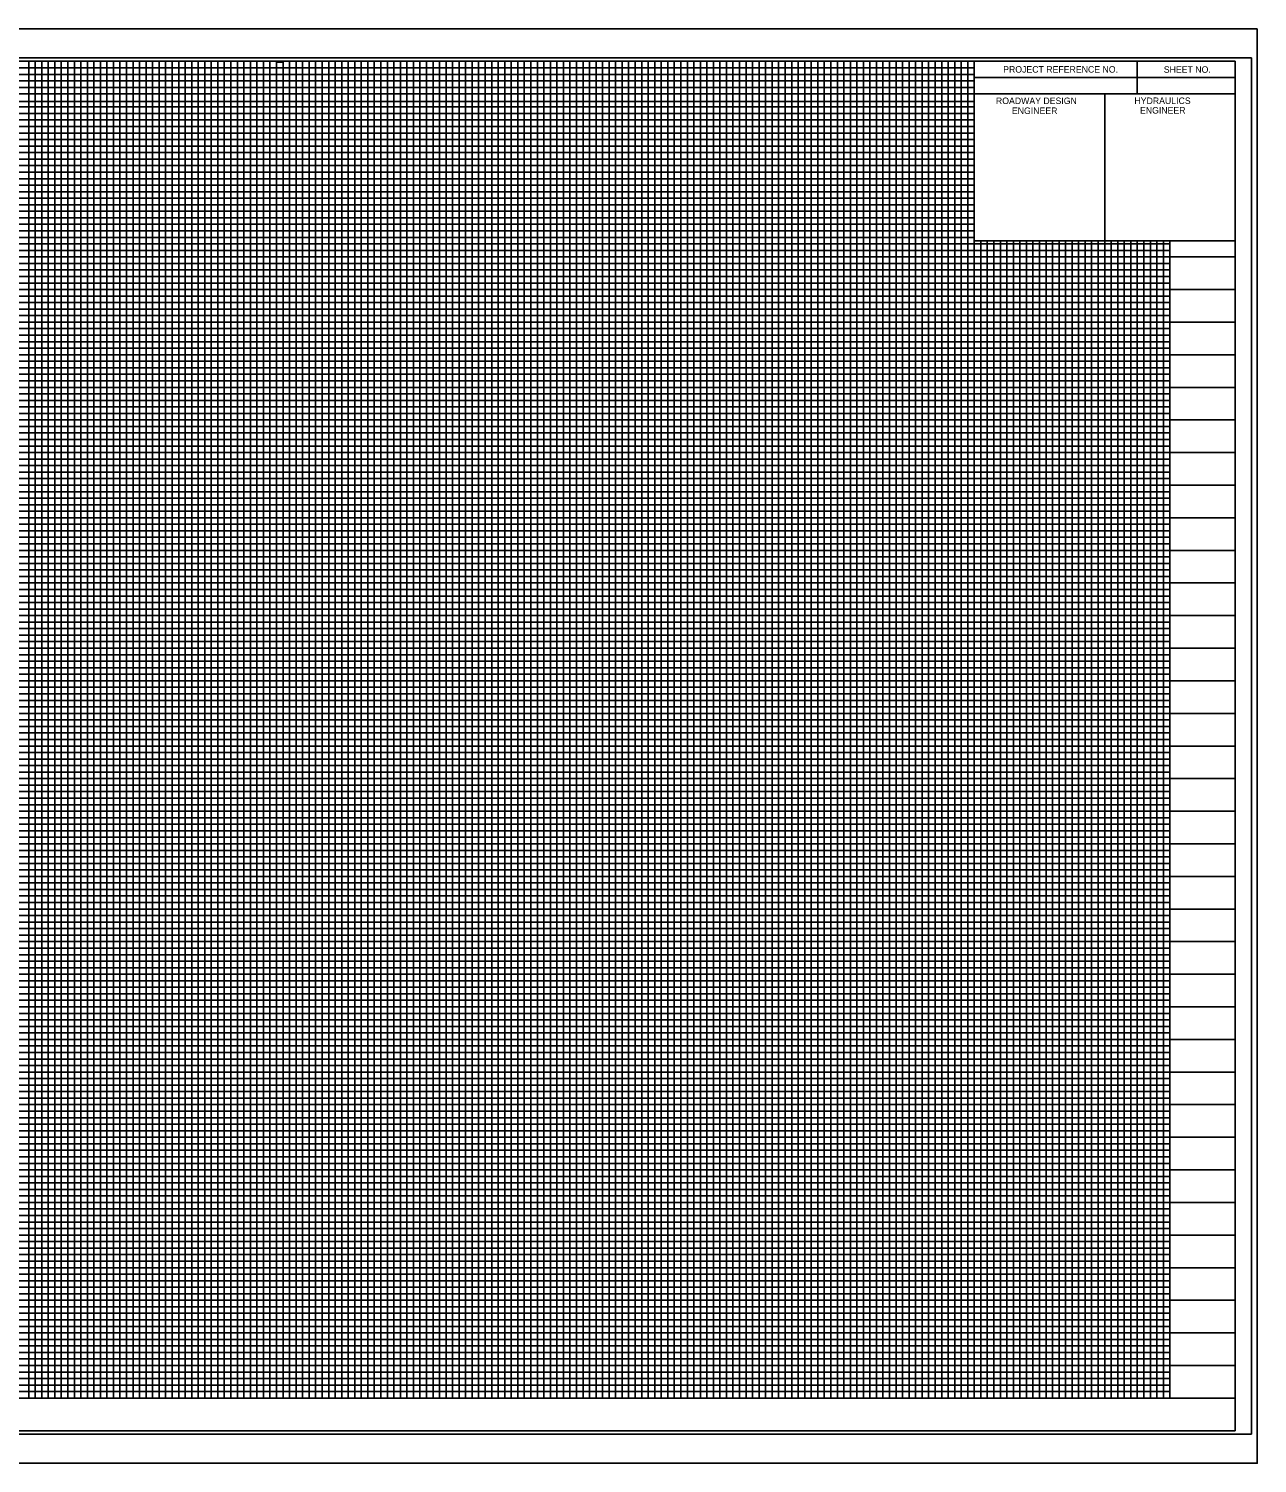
# Model space of a CAD drawing. Extents: x 2345490 to 2436403, y 465165 to 573888.
# Drawn here: x 2424020 to 2424962, y 508670 to 509770 of the extents above; entities that cross this region are included whole.
import ezdxf

# ---------------------------------------------------------------- set-up
doc = ezdxf.new("R2010")
doc.units = 0
for name, color, linetype in [('Old_Level_1', 7, 'Continuous'), ('Old_Level_18', 7, 'Continuous'), ('Old_Level_40', 7, 'Continuous'), ('Old_Level_41', 7, 'Continuous'), ('Old_Level_42', 7, 'Continuous'), ('Old_Level_43', 7, 'Continuous'), ('Old_Level_44', 7, 'Continuous'), ('Old_Level_50', 7, 'Continuous'), ('Old_Level_51', 7, 'Continuous'), ('Old_Level_52', 7, 'Continuous'), ('Old_Level_53', 7, 'Continuous')]:
    doc.layers.add(name, color=color, linetype=linetype)

msp = doc.modelspace()

# ---------------------------------------------------------------- linework, layer by layer
at = {"layer": 'Old_Level_1'}
msp.add_line((2424957.825, 509747.962), (2424957.825, 509747.962), dxfattribs=at)
at = {"layer": 'Old_Level_18'}
msp.add_lwpolyline([(2424945.325, 509745.412), (2423445.325, 509745.412), (2423445.325, 508695.412), (2424945.325, 508695.412)], close=True, dxfattribs=at)
at = {"layer": 'Old_Level_40'}
for p, q in [((2424870.325, 509745.362), (2424870.325, 509720.362)), ((2424745.275, 509732.862), (2424945.325, 509732.862)), ((2424845.325, 509720.362), (2424845.325, 509607.912))]:
    msp.add_line(p, q, dxfattribs=at)
for points in [[(2424745.275, 509745.412), (2424945.325, 509745.412), (2424945.325, 509720.362), (2424745.275, 509720.362)], [(2424745.275, 509720.362), (2424845.325, 509720.362), (2424845.325, 509607.862), (2424745.275, 509607.862)], [(2424845.325, 509720.362), (2424945.325, 509720.362), (2424945.325, 509607.862), (2424845.325, 509607.862)]]:
    msp.add_lwpolyline(points, close=True, dxfattribs=at)
at = {"layer": 'Old_Level_41'}
msp.add_line((2424945.325, 508720.412), (2423445.325, 508720.412), dxfattribs=at)
for points in [[(2423970.325, 508720.412), (2424020.325, 508720.412), (2424020.325, 509745.412), (2424070.325, 509745.412), (2424070.325, 508720.412), (2424120.325, 508720.412), (2424120.325, 509745.412), (2424170.325, 509745.412), (2424170.325, 508720.412), (2424220.325, 508720.412), (2424220.325, 509745.412), (2424270.325, 509745.412), (2424270.325, 508720.412), (2424320.325, 508720.412), (2424320.325, 509745.412), (2424370.325, 509745.412), (2424370.325, 508720.412), (2424420.325, 508720.412), (2424420.325, 509745.412), (2424470.325, 509745.412), (2424470.325, 508720.412), (2424520.325, 508720.412), (2424520.325, 509745.412), (2424570.325, 509745.412), (2424570.325, 508720.412), (2424620.325, 508720.412), (2424620.325, 509745.412), (2424670.325, 509745.412), (2424670.325, 508720.412), (2424720.325, 508720.412), (2424720.325, 509745.412)], [(2423995.325, 508720.412), (2424045.325, 508720.412), (2424045.325, 509745.412), (2424095.325, 509745.412), (2424095.325, 508720.412), (2424145.325, 508720.412), (2424145.325, 509745.412), (2424195.325, 509745.412), (2424195.325, 508720.412), (2424245.325, 508720.412), (2424245.325, 509745.412), (2424295.325, 509745.412), (2424295.325, 508720.412), (2424345.325, 508720.412), (2424345.325, 509745.412), (2424395.325, 509745.412), (2424395.325, 508720.412), (2424445.325, 508720.412), (2424445.325, 509745.412), (2424495.325, 509745.412), (2424495.325, 508720.412), (2424545.325, 508720.412), (2424545.325, 509745.412), (2424595.325, 509745.412), (2424595.325, 508720.412), (2424645.325, 508720.412), (2424645.325, 509745.412), (2424695.325, 509745.412), (2424695.325, 508720.412), (2424745.325, 508720.412), (2424745.325, 509745.412), (2424771.625, 509745.412)], [(2423445.325, 509695.412), (2424745.275, 509695.412)], [(2424745.275, 509645.412), (2423445.325, 509645.412), (2423445.325, 509595.362), (2424945.325, 509595.362)], [(2424945.325, 509570.412), (2423445.325, 509570.412), (2423445.325, 509620.412), (2424745.275, 509620.412)], [(2424770.325, 509607.862), (2424770.325, 508720.412), (2424820.325, 508720.412), (2424820.325, 509607.862)], [(2424870.325, 509607.862), (2424870.325, 508720.412)], [(2424945.325, 509545.412), (2423445.325, 509545.412), (2423445.325, 509495.412), (2424945.325, 509495.412)], [(2424945.325, 509470.412), (2423445.325, 509470.412), (2423445.325, 509520.412), (2424945.325, 509520.412)], [(2424945.325, 509445.412), (2423445.325, 509445.412), (2423445.325, 509395.412), (2424945.325, 509395.412)], [(2424945.325, 509345.412), (2423445.325, 509345.412), (2423445.325, 509295.412), (2424945.325, 509295.412)], [(2424945.325, 509245.412), (2423445.325, 509245.412), (2423445.325, 509195.412), (2424945.325, 509195.412)], [(2424945.325, 509145.412), (2423445.325, 509145.412), (2423445.325, 509095.412), (2424945.325, 509095.412)], [(2424945.325, 509070.412), (2423445.325, 509070.412), (2423445.325, 509120.412), (2424945.325, 509120.412)], [(2424945.325, 509045.412), (2423445.325, 509045.412), (2423445.325, 508995.412), (2424945.325, 508995.412)], [(2424945.325, 508970.412), (2423445.325, 508970.412), (2423445.325, 509020.412), (2424945.325, 509020.412)], [(2424945.325, 508945.412), (2423445.325, 508945.412), (2423445.325, 508895.412), (2424945.325, 508895.412)], [(2424945.325, 508845.412), (2423445.325, 508845.412), (2423445.325, 508795.412), (2424945.325, 508795.412)], [(2424945.325, 508770.412), (2423445.325, 508770.412), (2423445.325, 508820.412), (2424945.325, 508820.412)], [(2424945.325, 508745.412), (2423445.325, 508745.412)]]:
    msp.add_lwpolyline(points, dxfattribs=at)
at = {"layer": 'Old_Level_42'}
for points in [[(2424745.275, 509670.412), (2423445.425, 509670.412), (2423445.425, 509720.362), (2424745.275, 509720.362)], [(2424795.325, 509607.862), (2424795.325, 508720.412), (2424845.325, 508720.412), (2424845.325, 509607.862)], [(2424895.325, 509607.862), (2424895.325, 508720.412), (2424945.325, 508720.412)], [(2424945.325, 509370.412), (2423445.325, 509370.412), (2423445.325, 509420.412), (2424945.325, 509420.412)], [(2424945.325, 509270.412), (2423445.325, 509270.412), (2423445.325, 509320.412), (2424945.325, 509320.412)], [(2424945.325, 509170.412), (2423445.325, 509170.412), (2423445.325, 509220.412), (2424945.325, 509220.412)], [(2424945.325, 508870.412), (2423445.325, 508870.412), (2423445.325, 508920.412), (2424945.325, 508920.412)]]:
    msp.add_lwpolyline(points, dxfattribs=at)
at = {"layer": 'Old_Level_43'}
for p, q in [((2424895.325, 509565.412), (2423495.325, 509565.412)), ((2423495.325, 509560.412), (2424895.325, 509560.412)), ((2424895.325, 509540.412), (2423495.325, 509540.412))]:
    msp.add_line(p, q, dxfattribs=at)
for points in [[(2424745.275, 509740.412), (2423495.325, 509740.412), (2423495.325, 509735.412), (2424745.275, 509735.412)], [(2424025.325, 508720.412), (2424025.325, 509745.412), (2424030.325, 509745.412), (2424030.325, 508720.412), (2424035.325, 508720.412), (2424035.325, 509745.412), (2424040.325, 509745.412), (2424040.325, 508720.412), (2424050.325, 508720.412), (2424050.325, 509745.412), (2424055.325, 509745.412), (2424055.325, 508720.412), (2424055.325, 508720.412), (2424060.325, 508720.412), (2424060.325, 509745.412), (2424065.325, 509745.412), (2424065.325, 508720.412), (2424075.325, 508720.412), (2424075.325, 509745.412), (2424080.325, 509745.412), (2424080.325, 508720.412), (2424085.325, 508720.412), (2424085.325, 509745.412), (2424090.325, 509745.412), (2424090.325, 508720.412), (2424100.325, 508720.412), (2424100.325, 509745.412), (2424105.325, 509745.412), (2424105.325, 508720.412), (2424110.325, 508720.412), (2424110.325, 509745.412), (2424115.325, 509745.412), (2424115.325, 508720.412), (2424125.325, 508720.412), (2424125.325, 509745.412), (2424130.325, 509745.412), (2424130.325, 508720.412), (2424135.325, 508720.412), (2424135.325, 509745.412), (2424140.325, 509745.412), (2424140.325, 508720.412), (2424150.325, 508720.412), (2424150.325, 509745.412), (2424155.325, 509745.412), (2424155.325, 508720.412), (2424160.325, 508720.412), (2424160.325, 509745.412), (2424165.325, 509745.412), (2424165.325, 508720.412), (2424175.325, 508720.412), (2424175.325, 509745.412), (2424180.325, 509745.412), (2424180.325, 508720.412), (2424185.325, 508720.412), (2424185.325, 509745.412), (2424190.325, 509745.412), (2424190.325, 508720.412), (2424200.325, 508720.412), (2424200.325, 509745.412), (2424205.325, 509745.412), (2424205.325, 508720.412)], [(2424205.325, 508720.412), (2424210.325, 508720.412), (2424210.325, 509744.812), (2424215.325, 509744.812), (2424215.325, 508720.412), (2424225.325, 508720.412), (2424225.325, 509745.412), (2424230.325, 509745.412), (2424230.325, 508720.412), (2424235.325, 508720.412), (2424235.325, 509745.412), (2424240.325, 509745.412), (2424240.325, 508720.412), (2424250.325, 508720.412), (2424250.325, 509745.412), (2424255.325, 509745.412), (2424255.325, 508720.412), (2424260.325, 508720.412), (2424260.325, 509745.412), (2424265.325, 509745.412), (2424265.325, 508720.412), (2424275.325, 508720.412), (2424275.325, 509745.412), (2424280.325, 509745.412), (2424280.325, 508720.412), (2424285.325, 508720.412), (2424285.325, 509745.412), (2424290.325, 509745.412), (2424290.325, 508720.412), (2424300.325, 508720.412), (2424300.325, 509745.412), (2424305.325, 509745.412), (2424305.325, 508720.412), (2424310.325, 508720.412), (2424310.325, 509745.412), (2424315.325, 509745.412), (2424315.325, 508720.412), (2424325.325, 508720.412), (2424325.325, 509745.412), (2424330.325, 509745.412), (2424330.325, 508720.412), (2424335.325, 508720.412), (2424335.325, 509745.412), (2424340.325, 509745.412), (2424340.325, 508720.412), (2424350.325, 508720.412), (2424350.325, 509745.412), (2424355.325, 509745.412), (2424355.325, 508720.412), (2424360.325, 508720.412), (2424360.325, 509745.412), (2424365.325, 509745.412), (2424365.325, 508720.412), (2424375.325, 508720.412), (2424375.325, 509745.412), (2424380.325, 509745.412), (2424380.325, 508720.412), (2424385.325, 508720.412), (2424385.325, 509745.412), (2424390.325, 509745.412), (2424390.325, 508720.412), (2424400.325, 508720.412), (2424400.325, 509745.412), (2424405.325, 509745.412), (2424405.325, 508720.412), (2424410.325, 508720.412), (2424410.325, 509745.412), (2424415.325, 509745.412), (2424415.325, 508720.412), (2424425.325, 508720.412), (2424425.325, 509745.412), (2424430.325, 509745.412), (2424430.325, 508720.412), (2424435.325, 508720.412), (2424435.325, 509745.412), (2424440.325, 509745.412), (2424440.325, 508720.412), (2424450.325, 508720.412), (2424450.325, 509745.412), (2424455.325, 509745.412), (2424455.325, 508720.412), (2424460.325, 508720.412), (2424460.325, 509745.412), (2424465.325, 509745.412), (2424465.325, 508720.412), (2424475.325, 508720.412), (2424475.325, 509745.412), (2424480.325, 509745.412), (2424480.325, 508720.412), (2424485.325, 508720.412), (2424485.325, 509745.412), (2424490.325, 509745.412), (2424490.325, 508720.412), (2424500.325, 508720.412), (2424500.325, 509745.412), (2424505.325, 509745.412), (2424505.325, 508720.412), (2424510.325, 508720.412), (2424510.325, 509745.412), (2424515.325, 509745.412), (2424515.325, 508720.412)], [(2424515.325, 508720.412), (2424525.325, 508720.412), (2424525.325, 509745.412), (2424530.325, 509745.412), (2424530.325, 508720.412), (2424535.325, 508720.412), (2424535.325, 509745.412), (2424540.325, 509745.412), (2424540.325, 508720.412), (2424550.325, 508720.412), (2424550.325, 509745.412), (2424555.325, 509745.412), (2424555.325, 508720.412), (2424560.325, 508720.412), (2424560.325, 509745.412), (2424565.325, 509745.412), (2424565.325, 508720.412), (2424575.325, 508720.412), (2424575.325, 509745.412), (2424580.325, 509745.412), (2424580.325, 508720.412), (2424585.325, 508720.412), (2424585.325, 509745.412), (2424590.325, 509745.412), (2424590.325, 508720.412), (2424600.325, 508720.412), (2424600.325, 509745.412), (2424605.325, 509745.412), (2424605.325, 508720.412), (2424610.325, 508720.412), (2424610.325, 509745.412), (2424615.325, 509745.412), (2424615.325, 508720.412), (2424625.325, 508720.412), (2424625.325, 509745.412), (2424630.325, 509745.412), (2424630.325, 508720.412), (2424635.325, 508720.412), (2424635.325, 509745.412), (2424640.325, 509745.412), (2424640.325, 508720.412), (2424650.325, 508720.412), (2424650.325, 509745.412), (2424655.325, 509745.412), (2424655.325, 508720.412), (2424660.325, 508720.412), (2424660.325, 509745.412), (2424665.325, 509745.412), (2424665.325, 508720.412), (2424675.325, 508720.412), (2424675.325, 509745.412), (2424680.325, 509745.412), (2424680.325, 508720.412), (2424685.325, 508720.412), (2424685.325, 509745.412), (2424690.325, 509745.412), (2424690.325, 508720.412), (2424700.325, 508720.412), (2424700.325, 509745.412), (2424705.325, 509745.412), (2424705.325, 508720.412), (2424710.325, 508720.412), (2424710.325, 509745.412), (2424715.325, 509745.412), (2424715.325, 508720.412), (2424725.325, 508720.412), (2424725.325, 509745.412), (2424730.325, 509745.412), (2424730.325, 508720.412), (2424735.325, 508720.412), (2424735.325, 509745.412), (2424740.325, 509745.412), (2424740.325, 508720.412), (2424750.325, 508720.412), (2424750.325, 509607.862)], [(2424745.275, 509730.412), (2423495.325, 509730.412), (2423495.325, 509725.412), (2424745.275, 509725.412)], [(2424745.275, 509714.662), (2423496.325, 509714.662), (2423496.325, 509710.412), (2424745.275, 509710.412)], [(2424745.275, 509705.412), (2423495.325, 509705.412), (2423495.325, 509700.412), (2424745.275, 509700.412)], [(2424745.275, 509690.412), (2423495.325, 509690.412), (2423495.325, 509685.412), (2424745.275, 509685.412)], [(2424745.275, 509680.412), (2423495.325, 509680.412), (2423495.325, 509675.412), (2424745.275, 509675.412)], [(2424745.275, 509665.412), (2423495.325, 509665.412), (2423495.325, 509660.412), (2424745.275, 509660.412)], [(2424745.275, 509655.412), (2423495.325, 509655.412), (2423495.325, 509650.412), (2424745.275, 509650.412)], [(2424745.275, 509640.412), (2423495.325, 509640.412), (2423495.325, 509635.412), (2424745.275, 509635.412)], [(2424745.275, 509630.412), (2423495.325, 509630.412), (2423495.325, 509625.412), (2424745.275, 509625.412)], [(2424745.275, 509615.412), (2423495.325, 509615.412), (2423495.325, 509610.412), (2424745.275, 509610.412)], [(2424895.325, 509605.412), (2423495.325, 509605.412), (2423495.325, 509605.412), (2423495.325, 509585.412), (2424895.325, 509585.412)], [(2423495.325, 509600.412), (2424895.325, 509600.412)], [(2424755.325, 509607.862), (2424755.325, 508720.412), (2424760.325, 508720.412), (2424760.325, 509607.862)], [(2424765.325, 509607.862), (2424765.325, 508720.412), (2424775.325, 508720.412), (2424775.325, 509607.862)], [(2424780.325, 509607.862), (2424780.325, 508720.412), (2424785.325, 508720.412), (2424785.325, 509607.862)], [(2424790.325, 509607.862), (2424790.325, 508720.412), (2424800.325, 508720.412), (2424800.325, 509607.862)], [(2424805.325, 509607.862), (2424805.325, 508720.412), (2424810.325, 508720.412), (2424810.325, 509607.862)], [(2424815.325, 509607.862), (2424815.325, 508720.412), (2424825.325, 508720.412), (2424825.325, 509607.862)], [(2424830.325, 509607.862), (2424830.325, 508720.412)], [(2424830.325, 508720.412), (2424835.325, 508720.412), (2424835.325, 509607.862)], [(2424840.325, 509607.862), (2424840.325, 508720.412), (2424850.325, 508720.412), (2424850.325, 509607.862)], [(2424855.325, 509607.862), (2424855.325, 508720.412), (2424860.325, 508720.412), (2424860.325, 509607.862)], [(2424865.325, 509607.862), (2424865.325, 508720.412), (2424875.325, 508720.412), (2424875.325, 509607.862)], [(2424880.325, 509607.862), (2424880.325, 508720.412), (2424885.325, 508720.412), (2424885.325, 509607.862)], [(2424890.325, 509607.862), (2424890.325, 508720.412), (2424900.325, 508720.412)], [(2424895.325, 509590.412), (2423495.325, 509590.412)], [(2424895.325, 509580.412), (2423495.325, 509580.412), (2423495.325, 509575.412), (2424895.325, 509575.412)], [(2424895.325, 509555.412), (2423495.325, 509555.412), (2423495.325, 509550.412), (2424895.325, 509550.412)], [(2424895.325, 509535.412), (2423495.325, 509535.412), (2423495.325, 509530.412), (2424895.325, 509530.412)], [(2424895.325, 509525.412), (2423495.325, 509525.412)], [(2423495.325, 509515.412), (2424895.325, 509515.412)], [(2424895.325, 509510.412), (2423495.325, 509510.412), (2423495.325, 509505.412), (2424895.325, 509505.412)], [(2424895.325, 509500.412), (2423495.325, 509500.412), (2423495.325, 509490.412), (2424895.325, 509490.412)], [(2424895.325, 509485.412), (2423495.325, 509485.412), (2423495.325, 509480.412), (2424895.325, 509480.412)], [(2424895.325, 509475.412), (2423495.325, 509475.412), (2423495.325, 509465.412), (2424895.325, 509465.412)], [(2424895.325, 509460.412), (2423495.325, 509460.412), (2423495.325, 509455.412), (2424895.325, 509455.412)], [(2424895.325, 509450.412), (2423495.325, 509450.412), (2423495.325, 509440.412), (2424895.325, 509440.412)], [(2424895.325, 509435.412), (2423495.325, 509435.412), (2423495.325, 509430.412), (2424895.325, 509430.412)], [(2424895.325, 509425.412), (2423495.325, 509425.412), (2423495.325, 509415.412), (2424895.325, 509415.412)], [(2424895.325, 509410.412), (2423495.325, 509410.412), (2423495.325, 509405.412), (2424895.325, 509405.412)], [(2424895.325, 509400.412), (2423495.325, 509400.412), (2423495.325, 509390.412), (2424895.325, 509390.412)], [(2424895.325, 509385.412), (2423495.325, 509385.412), (2423495.325, 509380.412), (2424895.325, 509380.412)], [(2424895.325, 509375.412), (2423495.325, 509375.412), (2423495.325, 509365.412), (2424895.325, 509365.412)], [(2424895.325, 509360.412), (2423495.325, 509360.412), (2423495.325, 509355.412), (2424895.325, 509355.412)], [(2424895.325, 509350.412), (2423495.325, 509350.412), (2423495.325, 509340.412), (2424895.325, 509340.412)], [(2424895.325, 509335.412), (2423495.325, 509335.412), (2423495.325, 509330.412), (2424895.325, 509330.412)], [(2424895.325, 509325.412), (2423495.325, 509325.412), (2423495.325, 509315.412), (2424895.325, 509315.412)], [(2424895.325, 509310.412), (2423495.325, 509310.412), (2423495.325, 509305.412), (2424895.325, 509305.412)], [(2424895.325, 509300.412), (2423495.325, 509300.412), (2423495.325, 509290.412), (2424895.325, 509290.412)], [(2424895.325, 509285.412), (2423495.325, 509285.412), (2423495.325, 509280.412), (2424895.325, 509280.412)], [(2424895.325, 509275.412), (2423495.325, 509275.412), (2423495.325, 509265.412), (2424895.325, 509265.412)], [(2424895.325, 509260.412), (2423495.325, 509260.412), (2423495.325, 509255.412), (2424895.325, 509255.412)], [(2424895.325, 509250.412), (2423495.325, 509250.412), (2423495.325, 509240.412), (2424895.325, 509240.412)], [(2424895.325, 509235.412), (2423495.325, 509235.412), (2423495.325, 509230.412), (2424895.325, 509230.412)], [(2424895.325, 509225.412), (2423495.325, 509225.412)], [(2423495.325, 509215.412), (2424895.325, 509215.412)], [(2424895.325, 509210.412), (2423495.325, 509210.412), (2423495.325, 509205.412), (2424895.325, 509205.412)], [(2424895.325, 509200.412), (2423495.325, 509200.412), (2423495.325, 509190.412), (2424895.325, 509190.412)], [(2424895.325, 509185.412), (2423495.325, 509185.412), (2423495.325, 509180.412), (2424895.325, 509180.412)], [(2424895.325, 509175.412), (2423495.325, 509175.412), (2423495.325, 509165.412), (2424895.325, 509165.412)], [(2424895.325, 509160.412), (2423495.325, 509160.412), (2423495.325, 509155.412), (2424895.325, 509155.412)], [(2424895.325, 509150.412), (2423495.325, 509150.412), (2423495.325, 509140.412), (2424895.325, 509140.412)], [(2424895.325, 509135.412), (2423495.325, 509135.412), (2423495.325, 509130.412), (2424895.325, 509130.412)], [(2424895.325, 509125.412), (2423495.325, 509125.412), (2423495.325, 509115.412), (2424895.325, 509115.412)], [(2424895.325, 509110.412), (2423495.325, 509110.412), (2423495.325, 509105.412), (2424895.325, 509105.412)], [(2424895.325, 509100.412), (2423495.325, 509100.412), (2423495.325, 509090.412), (2424895.325, 509090.412)], [(2424895.325, 509085.412), (2423495.325, 509085.412), (2423495.325, 509080.412), (2424895.325, 509080.412)], [(2424895.325, 509075.412), (2423495.325, 509075.412), (2423495.325, 509065.412), (2424895.325, 509065.412)], [(2424895.325, 509060.412), (2423495.325, 509060.412), (2423495.325, 509055.412), (2424895.325, 509055.412)], [(2424895.325, 509050.412), (2423495.325, 509050.412), (2423495.325, 509040.412), (2424895.325, 509040.412)], [(2424895.325, 509035.412), (2423495.325, 509035.412), (2423495.325, 509030.412), (2424895.325, 509030.412)], [(2424895.325, 509025.412), (2423495.325, 509025.412), (2423495.325, 509015.412), (2424895.325, 509015.412)], [(2424895.325, 509010.412), (2423495.325, 509010.412), (2423495.325, 509005.412), (2424895.325, 509005.412)], [(2424895.325, 509000.412), (2423495.325, 509000.412), (2423495.325, 508990.412), (2424895.325, 508990.412)], [(2424895.325, 508985.412), (2423495.325, 508985.412), (2423495.325, 508980.412), (2424895.325, 508980.412)], [(2424895.325, 508975.412), (2423495.325, 508975.412), (2423495.325, 508965.412), (2424895.325, 508965.412)], [(2424895.325, 508960.412), (2423495.325, 508960.412), (2423495.325, 508955.412), (2424895.325, 508955.412)], [(2424895.325, 508950.412), (2423495.325, 508950.412), (2423495.325, 508940.412), (2424895.325, 508940.412)], [(2424895.325, 508935.412), (2423495.325, 508935.412), (2423495.325, 508930.412), (2424895.325, 508930.412)], [(2424895.325, 508925.412), (2423495.325, 508925.412)], [(2423495.325, 508915.412), (2424895.325, 508915.412)], [(2424895.325, 508910.412), (2423495.325, 508910.412), (2423495.325, 508905.412), (2424895.325, 508905.412)], [(2424895.325, 508900.412), (2423495.325, 508900.412)], [(2423495.325, 508890.412), (2424895.325, 508890.412)], [(2424895.325, 508885.412), (2423495.325, 508885.412), (2423495.325, 508880.412), (2424895.325, 508880.412)], [(2424895.325, 508875.412), (2423495.325, 508875.412), (2423495.325, 508865.412), (2424895.325, 508865.412)], [(2424895.325, 508860.412), (2423495.325, 508860.412), (2423495.325, 508855.412), (2424895.325, 508855.412)], [(2424895.325, 508850.412), (2423495.325, 508850.412), (2423495.325, 508840.412), (2424895.325, 508840.412)], [(2424895.325, 508835.412), (2423495.325, 508835.412), (2423495.325, 508830.412), (2424895.325, 508830.412)], [(2424895.325, 508825.412), (2423495.325, 508825.412), (2423495.325, 508815.412), (2424895.325, 508815.412)], [(2424895.325, 508810.412), (2423495.325, 508810.412), (2423495.325, 508805.412), (2424895.325, 508805.412)], [(2424895.325, 508800.412), (2423495.325, 508800.412), (2423495.325, 508790.412), (2424895.325, 508790.412)], [(2424895.325, 508785.412), (2423495.325, 508785.412), (2423495.325, 508780.412), (2424895.325, 508780.412)], [(2424895.325, 508775.412), (2423495.325, 508775.412), (2423495.325, 508765.412), (2424895.325, 508765.412)], [(2424895.325, 508760.412), (2423495.325, 508760.412), (2423495.325, 508755.412), (2424895.325, 508755.412)], [(2424895.325, 508750.412), (2423495.325, 508750.412), (2423495.325, 508740.412), (2424895.325, 508740.412)], [(2424895.325, 508735.412), (2423495.325, 508735.412), (2423495.325, 508730.412), (2424895.325, 508730.412)], [(2424895.325, 508725.412), (2423495.325, 508725.412)]]:
    msp.add_lwpolyline(points, dxfattribs=at)
at = {"layer": 'Old_Level_50'}
msp.add_line((2424962.325, 509770.412), (2424962.325, 509770.412), dxfattribs=at)
msp.add_lwpolyline([(2424957.825, 509747.962), (2423291.325, 509747.962), (2423291.325, 508692.862), (2424957.825, 508692.862)], close=True, dxfattribs=at)
at = {"layer": 'Old_Level_51'}
msp.add_lwpolyline([(2424962.325, 509770.412), (2423278.325, 509770.412), (2423278.325, 508670.412), (2424962.325, 508670.412)], close=True, dxfattribs=at)
at = {"layer": 'Old_Level_52'}
msp.add_line((2424957.825, 509747.962), (2424957.825, 509747.962), dxfattribs=at)
at = {"layer": 'Old_Level_53'}
msp.add_line((2424957.825, 509747.962), (2424957.825, 509747.962), dxfattribs=at)

# ---------------------------------------------------------------- texts
at = {"layer": 'Old_Level_44'}
for s, p in [('PROJECT REFERENCE NO.', (2424767.475, 509736.712)), ('SHEET NO.', (2424890.625, 509736.612)), ('ROADWAY DESIGN', (2424761.925, 509712.612)), ('ENGINEER', (2424774.175, 509705.012)), ('HYDRAULICS', (2424868.125, 509712.662)), ('ENGINEER', (2424872.375, 509705.312))]:
    msp.add_text(s, height=5.0001, dxfattribs=at).set_placement(p)

doc.saveas('drawing.dxf')
